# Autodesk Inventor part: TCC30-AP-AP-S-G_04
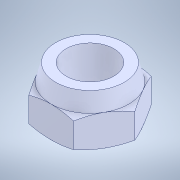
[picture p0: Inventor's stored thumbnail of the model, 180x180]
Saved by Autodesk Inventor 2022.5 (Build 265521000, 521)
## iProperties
Created: 2023-09
Part Number: TCC30-AP-AP-S-G_04
Material: 一般
Document SubType Name: Modeling
Designer: ImaoCorp
Density: 1 g/cm^3
Appearance: 既定
Author: ImaoCorp
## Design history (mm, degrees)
feature "TCC30-AP-AP-S-G_04"
node "ソリッド1"
